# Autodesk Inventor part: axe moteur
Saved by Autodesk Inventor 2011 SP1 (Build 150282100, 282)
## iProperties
Created: 2010-12
Part Number: axe moteur
Document SubType Name: Modeling
Designer: eric
Density: 1 g/cm^3
Author: eric
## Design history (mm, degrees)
feature "Base1"
node "Solide1"
node "Corps solides"
node "Corps surfaciques"
